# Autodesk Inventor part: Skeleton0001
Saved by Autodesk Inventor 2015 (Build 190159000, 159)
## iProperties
Created: 2015-04
Part Number: Skeleton0001
Material: Aluminum 6061
Document SubType Name: Modeling
Designer: suporte
Density: 2.7 g/cm^3
Appearance: Aluminum - Flat
_SkeletonDoc: Frame Skeleton File
_Version: 15.0.0
Author: suporte
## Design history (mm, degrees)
sketch "Reference Skeleton"
